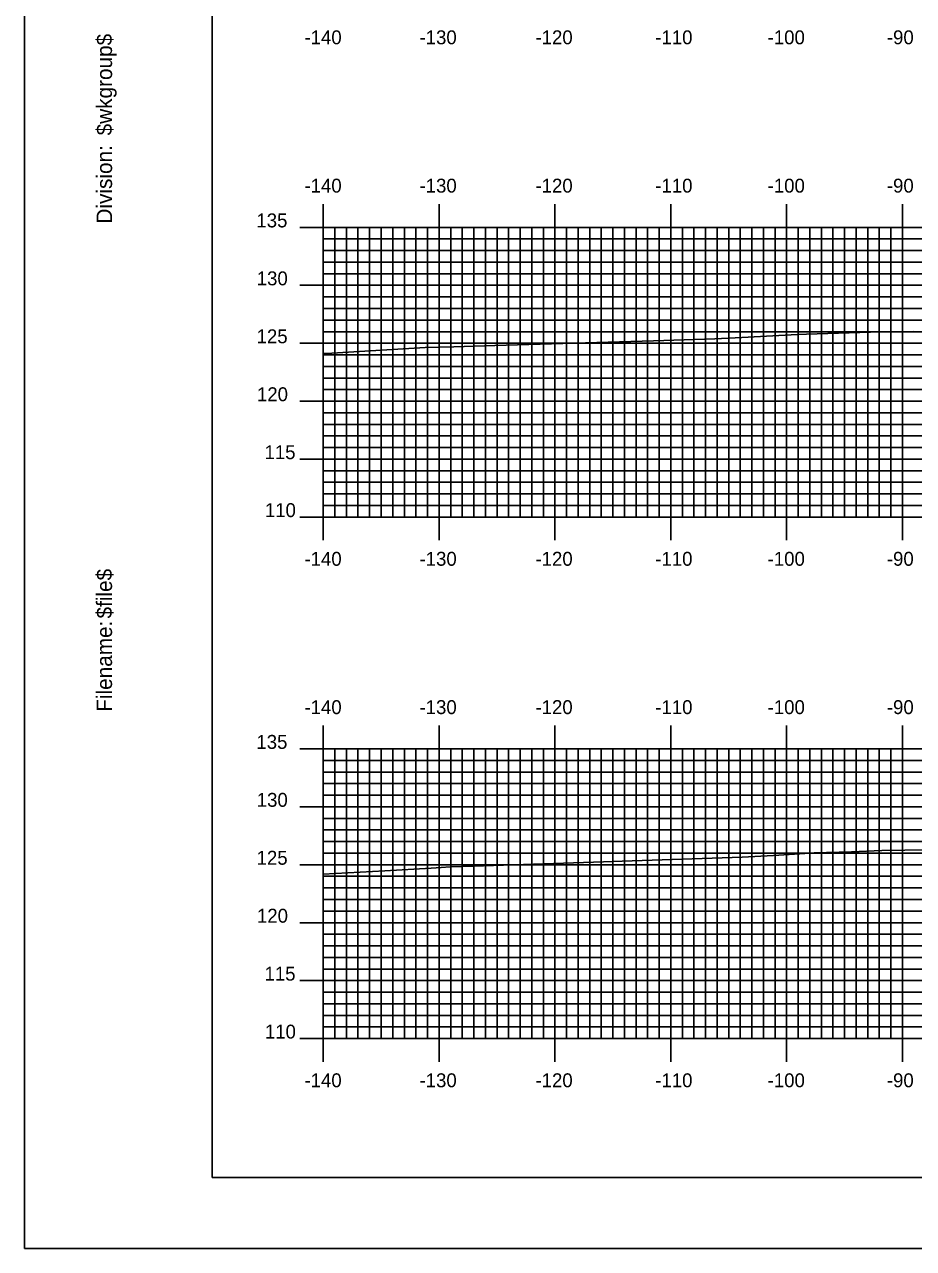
# Model space of a CAD drawing. Extents: x 842569 to 842912, y 363538 to 363758.
# Drawn here: x 842568.6 to 842645.4, y 363537.6 to 363643.2 of the extents above; entities that cross this region are included whole.
import ezdxf

# ---------------------------------------------------------------- set-up
doc = ezdxf.new("R2010")
doc.units = 0
for name, color, linetype in [('BORDER', 7, 'Continuous'), ('H_V ANNOTATION', 7, 'Continuous'), ('M_Roadway_Centerline', 7, 'Continuous'), ('MAJOR', 7, 'Continuous'), ('MINOR', 7, 'Continuous'), ('PLOT BOUNDARY', 7, 'Continuous'), ('S_Roadway_Centerline', 7, 'Continuous')]:
    doc.layers.add(name, color=color, linetype=linetype)

msp = doc.modelspace()

# ---------------------------------------------------------------- linework, layer by layer
at = {"layer": 'BORDER'}
msp.add_lwpolyline([(842584.8, 363543.72), (842904.8, 363543.72), (842904.8, 363753.72), (842584.8, 363753.72)], close=True, dxfattribs=at)
at = {"layer": 'MAJOR'}
for p, q in [((842594.4, 363627.73), (842594.4, 363625.72)), ((842604.4, 363627.73), (842604.4, 363625.72)), ((842614.4, 363627.73), (842614.4, 363625.72)), ((842624.4, 363627.73), (842624.4, 363625.72)), ((842634.4, 363627.73), (842634.4, 363625.72)), ((842644.4, 363627.73), (842644.4, 363625.72)), ((842592.39, 363625.72), (842594.4, 363625.72)), ((842594.4, 363625.72), (842874.4, 363625.72)), ((842594.4, 363600.72), (842594.4, 363625.72)), ((842594.4, 363600.72), (842594.4, 363625.72)), ((842594.4, 363625.72), (842874.4, 363625.72)), ((842604.4, 363600.72), (842604.4, 363625.72)), ((842614.4, 363600.72), (842614.4, 363625.72)), ((842624.4, 363600.72), (842624.4, 363625.72)), ((842634.4, 363600.72), (842634.4, 363625.72)), ((842644.4, 363600.72), (842644.4, 363625.72)), ((842592.39, 363620.72), (842594.4, 363620.72)), ((842594.4, 363620.72), (842874.4, 363620.72)), ((842592.39, 363615.72), (842594.4, 363615.72)), ((842594.4, 363615.72), (842874.4, 363615.72)), ((842592.39, 363610.72), (842594.4, 363610.72)), ((842594.4, 363610.72), (842874.4, 363610.72)), ((842592.39, 363605.72), (842594.4, 363605.72)), ((842594.4, 363605.72), (842874.4, 363605.72)), ((842592.39, 363600.72), (842594.4, 363600.72)), ((842594.4, 363600.72), (842874.4, 363600.72)), ((842594.4, 363600.72), (842874.4, 363600.72)), ((842594.4, 363598.72), (842594.4, 363600.72)), ((842604.4, 363598.72), (842604.4, 363600.72)), ((842614.4, 363598.72), (842614.4, 363600.72)), ((842624.4, 363598.72), (842624.4, 363600.72)), ((842634.4, 363598.72), (842634.4, 363600.72)), ((842644.4, 363598.72), (842644.4, 363600.72)), ((842594.4, 363582.73), (842594.4, 363580.72)), ((842604.4, 363582.73), (842604.4, 363580.72)), ((842614.4, 363582.73), (842614.4, 363580.72)), ((842624.4, 363582.73), (842624.4, 363580.72)), ((842634.4, 363582.73), (842634.4, 363580.72)), ((842644.4, 363582.73), (842644.4, 363580.72)), ((842592.39, 363580.72), (842594.4, 363580.72)), ((842594.4, 363580.72), (842874.4, 363580.72)), ((842594.4, 363555.72), (842594.4, 363580.72)), ((842594.4, 363555.72), (842594.4, 363580.72)), ((842594.4, 363580.72), (842874.4, 363580.72)), ((842604.4, 363555.72), (842604.4, 363580.72)), ((842614.4, 363555.72), (842614.4, 363580.72)), ((842624.4, 363555.72), (842624.4, 363580.72)), ((842634.4, 363555.72), (842634.4, 363580.72)), ((842644.4, 363555.72), (842644.4, 363580.72)), ((842592.39, 363575.72), (842594.4, 363575.72)), ((842594.4, 363575.72), (842874.4, 363575.72)), ((842592.39, 363570.72), (842594.4, 363570.72)), ((842594.4, 363570.72), (842874.4, 363570.72)), ((842592.39, 363565.72), (842594.4, 363565.72)), ((842594.4, 363565.72), (842874.4, 363565.72)), ((842592.39, 363560.72), (842594.4, 363560.72)), ((842594.4, 363560.72), (842874.4, 363560.72)), ((842592.39, 363555.72), (842594.4, 363555.72)), ((842594.4, 363555.72), (842874.4, 363555.72)), ((842594.4, 363555.72), (842874.4, 363555.72)), ((842594.4, 363553.72), (842594.4, 363555.72)), ((842604.4, 363553.72), (842604.4, 363555.72)), ((842614.4, 363553.72), (842614.4, 363555.72)), ((842624.4, 363553.72), (842624.4, 363555.72)), ((842634.4, 363553.72), (842634.4, 363555.72)), ((842644.4, 363553.72), (842644.4, 363555.72))]:
    msp.add_line(p, q, dxfattribs=at)
at = {"layer": 'MINOR'}
for p, q in [((842595.4, 363600.72), (842595.4, 363625.72)), ((842596.4, 363600.72), (842596.4, 363625.72)), ((842597.4, 363600.72), (842597.4, 363625.72)), ((842598.4, 363600.72), (842598.4, 363625.72)), ((842599.4, 363600.72), (842599.4, 363625.72)), ((842600.4, 363600.72), (842600.4, 363625.72)), ((842601.4, 363600.72), (842601.4, 363625.72)), ((842602.4, 363600.72), (842602.4, 363625.72)), ((842603.4, 363600.72), (842603.4, 363625.72)), ((842605.4, 363600.72), (842605.4, 363625.72)), ((842606.4, 363600.72), (842606.4, 363625.72)), ((842607.4, 363600.72), (842607.4, 363625.72)), ((842608.4, 363600.72), (842608.4, 363625.72)), ((842609.4, 363600.72), (842609.4, 363625.72)), ((842610.4, 363600.72), (842610.4, 363625.72)), ((842611.4, 363600.72), (842611.4, 363625.72)), ((842612.4, 363600.72), (842612.4, 363625.72)), ((842613.4, 363600.72), (842613.4, 363625.72)), ((842615.4, 363600.72), (842615.4, 363625.72)), ((842616.4, 363600.72), (842616.4, 363625.72)), ((842617.4, 363600.72), (842617.4, 363625.72)), ((842618.4, 363600.72), (842618.4, 363625.72)), ((842619.4, 363600.72), (842619.4, 363625.72)), ((842620.4, 363600.72), (842620.4, 363625.72)), ((842621.4, 363600.72), (842621.4, 363625.72)), ((842622.4, 363600.72), (842622.4, 363625.72)), ((842623.4, 363600.72), (842623.4, 363625.72)), ((842625.4, 363600.72), (842625.4, 363625.72)), ((842626.4, 363600.72), (842626.4, 363625.72)), ((842627.4, 363600.72), (842627.4, 363625.72)), ((842628.4, 363600.72), (842628.4, 363625.72)), ((842629.4, 363600.72), (842629.4, 363625.72)), ((842630.4, 363600.72), (842630.4, 363625.72)), ((842631.4, 363600.72), (842631.4, 363625.72)), ((842632.4, 363600.72), (842632.4, 363625.72)), ((842633.4, 363600.72), (842633.4, 363625.72)), ((842635.4, 363600.72), (842635.4, 363625.72)), ((842636.4, 363600.72), (842636.4, 363625.72)), ((842637.4, 363600.72), (842637.4, 363625.72)), ((842638.4, 363600.72), (842638.4, 363625.72)), ((842639.4, 363600.72), (842639.4, 363625.72)), ((842640.4, 363600.72), (842640.4, 363625.72)), ((842641.4, 363600.72), (842641.4, 363625.72)), ((842642.4, 363600.72), (842642.4, 363625.72)), ((842643.4, 363600.72), (842643.4, 363625.72)), ((842594.4, 363624.72), (842874.4, 363624.72)), ((842594.4, 363624.72), (842596.4, 363624.72)), ((842594.4, 363623.72), (842874.4, 363623.72)), ((842594.4, 363623.72), (842596.4, 363623.72)), ((842594.4, 363622.72), (842874.4, 363622.72)), ((842594.4, 363622.72), (842596.4, 363622.72)), ((842594.4, 363621.72), (842874.4, 363621.72)), ((842594.4, 363621.72), (842596.4, 363621.72)), ((842594.4, 363619.72), (842874.4, 363619.72)), ((842594.4, 363619.72), (842596.4, 363619.72)), ((842594.4, 363618.72), (842874.4, 363618.72)), ((842594.4, 363618.72), (842596.4, 363618.72)), ((842594.4, 363617.72), (842874.4, 363617.72)), ((842594.4, 363617.72), (842596.4, 363617.72)), ((842594.4, 363616.72), (842874.4, 363616.72)), ((842594.4, 363616.72), (842596.4, 363616.72)), ((842594.4, 363614.72), (842874.4, 363614.72)), ((842594.4, 363614.72), (842596.4, 363614.72)), ((842594.4, 363613.72), (842874.4, 363613.72)), ((842594.4, 363613.72), (842596.4, 363613.72)), ((842594.4, 363612.72), (842874.4, 363612.72)), ((842594.4, 363612.72), (842596.4, 363612.72)), ((842594.4, 363611.72), (842874.4, 363611.72)), ((842594.4, 363611.72), (842596.4, 363611.72)), ((842594.4, 363609.72), (842874.4, 363609.72)), ((842594.4, 363609.72), (842596.4, 363609.72)), ((842594.4, 363608.72), (842874.4, 363608.72)), ((842594.4, 363608.72), (842596.4, 363608.72)), ((842594.4, 363607.72), (842874.4, 363607.72)), ((842594.4, 363607.72), (842596.4, 363607.72)), ((842594.4, 363606.72), (842874.4, 363606.72)), ((842594.4, 363606.72), (842596.4, 363606.72)), ((842594.4, 363604.72), (842874.4, 363604.72)), ((842594.4, 363604.72), (842596.4, 363604.72)), ((842594.4, 363603.72), (842874.4, 363603.72)), ((842594.4, 363603.72), (842596.4, 363603.72)), ((842594.4, 363602.72), (842874.4, 363602.72)), ((842594.4, 363602.72), (842596.4, 363602.72)), ((842594.4, 363601.72), (842874.4, 363601.72)), ((842594.4, 363601.72), (842596.4, 363601.72)), ((842595.4, 363555.72), (842595.4, 363580.72)), ((842596.4, 363555.72), (842596.4, 363580.72)), ((842597.4, 363555.72), (842597.4, 363580.72)), ((842598.4, 363555.72), (842598.4, 363580.72)), ((842599.4, 363555.72), (842599.4, 363580.72)), ((842600.4, 363555.72), (842600.4, 363580.72)), ((842601.4, 363555.72), (842601.4, 363580.72)), ((842602.4, 363555.72), (842602.4, 363580.72)), ((842603.4, 363555.72), (842603.4, 363580.72)), ((842605.4, 363555.72), (842605.4, 363580.72)), ((842606.4, 363555.72), (842606.4, 363580.72)), ((842607.4, 363555.72), (842607.4, 363580.72)), ((842608.4, 363555.72), (842608.4, 363580.72)), ((842609.4, 363555.72), (842609.4, 363580.72)), ((842610.4, 363555.72), (842610.4, 363580.72)), ((842611.4, 363555.72), (842611.4, 363580.72)), ((842612.4, 363555.72), (842612.4, 363580.72)), ((842613.4, 363555.72), (842613.4, 363580.72)), ((842615.4, 363555.72), (842615.4, 363580.72)), ((842616.4, 363555.72), (842616.4, 363580.72)), ((842617.4, 363555.72), (842617.4, 363580.72)), ((842618.4, 363555.72), (842618.4, 363580.72)), ((842619.4, 363555.72), (842619.4, 363580.72)), ((842620.4, 363555.72), (842620.4, 363580.72)), ((842621.4, 363555.72), (842621.4, 363580.72)), ((842622.4, 363555.72), (842622.4, 363580.72)), ((842623.4, 363555.72), (842623.4, 363580.72)), ((842625.4, 363555.72), (842625.4, 363580.72)), ((842626.4, 363555.72), (842626.4, 363580.72)), ((842627.4, 363555.72), (842627.4, 363580.72)), ((842628.4, 363555.72), (842628.4, 363580.72)), ((842629.4, 363555.72), (842629.4, 363580.72)), ((842630.4, 363555.72), (842630.4, 363580.72)), ((842631.4, 363555.72), (842631.4, 363580.72)), ((842632.4, 363555.72), (842632.4, 363580.72)), ((842633.4, 363555.72), (842633.4, 363580.72)), ((842635.4, 363555.72), (842635.4, 363580.72)), ((842636.4, 363555.72), (842636.4, 363580.72)), ((842637.4, 363555.72), (842637.4, 363580.72)), ((842638.4, 363555.72), (842638.4, 363580.72)), ((842639.4, 363555.72), (842639.4, 363580.72)), ((842640.4, 363555.72), (842640.4, 363580.72)), ((842641.4, 363555.72), (842641.4, 363580.72)), ((842642.4, 363555.72), (842642.4, 363580.72)), ((842643.4, 363555.72), (842643.4, 363580.72)), ((842594.4, 363579.72), (842874.4, 363579.72)), ((842594.4, 363579.72), (842596.4, 363579.72)), ((842594.4, 363578.72), (842874.4, 363578.72)), ((842594.4, 363578.72), (842596.4, 363578.72)), ((842594.4, 363577.72), (842874.4, 363577.72)), ((842594.4, 363577.72), (842596.4, 363577.72)), ((842594.4, 363576.72), (842874.4, 363576.72)), ((842594.4, 363576.72), (842596.4, 363576.72)), ((842594.4, 363574.72), (842874.4, 363574.72)), ((842594.4, 363574.72), (842596.4, 363574.72)), ((842594.4, 363573.72), (842874.4, 363573.72)), ((842594.4, 363573.72), (842596.4, 363573.72)), ((842594.4, 363572.72), (842874.4, 363572.72)), ((842594.4, 363572.72), (842596.4, 363572.72)), ((842594.4, 363571.72), (842874.4, 363571.72)), ((842594.4, 363571.72), (842596.4, 363571.72)), ((842594.4, 363569.72), (842874.4, 363569.72)), ((842594.4, 363569.72), (842596.4, 363569.72)), ((842594.4, 363568.72), (842874.4, 363568.72)), ((842594.4, 363568.72), (842596.4, 363568.72)), ((842594.4, 363567.72), (842874.4, 363567.72)), ((842594.4, 363567.72), (842596.4, 363567.72)), ((842594.4, 363566.72), (842874.4, 363566.72)), ((842594.4, 363566.72), (842596.4, 363566.72)), ((842594.4, 363564.72), (842874.4, 363564.72)), ((842594.4, 363564.72), (842596.4, 363564.72)), ((842594.4, 363563.72), (842874.4, 363563.72)), ((842594.4, 363563.72), (842596.4, 363563.72)), ((842594.4, 363562.72), (842874.4, 363562.72)), ((842594.4, 363562.72), (842596.4, 363562.72)), ((842594.4, 363561.72), (842874.4, 363561.72)), ((842594.4, 363561.72), (842596.4, 363561.72)), ((842594.4, 363559.72), (842874.4, 363559.72)), ((842594.4, 363559.72), (842596.4, 363559.72)), ((842594.4, 363558.72), (842874.4, 363558.72)), ((842594.4, 363558.72), (842596.4, 363558.72)), ((842594.4, 363557.72), (842874.4, 363557.72)), ((842594.4, 363557.72), (842596.4, 363557.72)), ((842594.4, 363556.72), (842874.4, 363556.72)), ((842594.4, 363556.72), (842596.4, 363556.72))]:
    msp.add_line(p, q, dxfattribs=at)
at = {"layer": 'PLOT BOUNDARY'}
msp.add_lwpolyline([(842568.61, 363537.6), (842908.61, 363537.6), (842908.61, 363757.6), (842568.61, 363757.6)], close=True, dxfattribs=at)
at = {"layer": 'S_Roadway_Centerline'}
for points in [[(842594.4, 363614.84), (842594.67, 363614.85), (842603.19, 363615.35), (842605.68, 363615.4), (842609.21, 363615.53), (842622.91, 363615.93), (842628.21, 363616.1), (842630.53, 363616.21), (842635.34, 363616.49), (842636.1, 363616.5), (842641.63, 363616.69), (842645.37, 363616.74)], [(842594.4, 363569.91), (842599.72, 363570.2), (842603.71, 363570.41), (842604.58, 363570.47), (842605.36, 363570.55), (842607.36, 363570.61), (842618.6, 363570.98), (842619.33, 363571), (842630.56, 363571.38), (842633.26, 363571.51), (842636.44, 363571.72), (842636.78, 363571.76), (842640, 363571.84), (842642.61, 363571.95), (842646.59, 363572.01)]]:
    msp.add_lwpolyline(points, dxfattribs=at)

# ---------------------------------------------------------------- texts
at = {"layer": 'BORDER'}
for s, p in [('$wkgroup$', (842576.17, 363633.66)), ('Division:', (842576.17, 363626.05)), ('$file$', (842576.17, 363591.97)), ('Filename:', (842576.17, 363583.92))]:
    msp.add_text(s, height=1.339, rotation=90, dxfattribs=at).set_placement(p)
at = {"layer": 'H_V ANNOTATION'}
for s, p in [('-140', (842592.78, 363641.52)), ('-130', (842602.71, 363641.52)), ('-120', (842612.72, 363641.52)), ('-110', (842623.06, 363641.52)), ('-100', (842632.76, 363641.52)), ('-90', (842643.05, 363641.52)), ('-140', (842592.78, 363628.72)), ('-130', (842602.71, 363628.72)), ('-120', (842612.72, 363628.72)), ('-110', (842623.06, 363628.72)), ('-100', (842632.76, 363628.72)), ('-90', (842643.05, 363628.72)), ('135', (842588.63, 363625.72)), ('130', (842588.66, 363620.72)), ('125', (842588.65, 363615.72)), ('120', (842588.68, 363610.72)), ('115', (842589.33, 363605.72)), ('110', (842589.36, 363600.72)), ('-140', (842592.78, 363596.52)), ('-130', (842602.71, 363596.52)), ('-120', (842612.72, 363596.52)), ('-110', (842623.06, 363596.52)), ('-100', (842632.76, 363596.52)), ('-90', (842643.05, 363596.52)), ('-140', (842592.78, 363583.72)), ('-130', (842602.71, 363583.72)), ('-120', (842612.72, 363583.72)), ('-110', (842623.06, 363583.72)), ('-100', (842632.76, 363583.72)), ('-90', (842643.05, 363583.72)), ('135', (842588.63, 363580.72)), ('130', (842588.66, 363575.72)), ('125', (842588.65, 363570.72)), ('120', (842588.68, 363565.72)), ('115', (842589.33, 363560.72)), ('110', (842589.36, 363555.72)), ('-140', (842592.78, 363551.52)), ('-130', (842602.71, 363551.52)), ('-120', (842612.72, 363551.52)), ('-110', (842623.06, 363551.52)), ('-100', (842632.76, 363551.52)), ('-90', (842643.05, 363551.52))]:
    msp.add_text(s, height=1.2, dxfattribs=at).set_placement(p)
at = {"layer": 'M_Roadway_Centerline'}
for s, p in [('C', (842635.34, 363616.49)), ('L', (842635.34, 363616.48)), ('C', (842603.19, 363615.35)), ('L', (842603.19, 363615.34)), ('C', (842636.77, 363571.76)), ('L', (842636.78, 363571.75)), ('C', (842605.36, 363570.55)), ('L', (842605.36, 363570.54))]:
    msp.add_text(s, height=0.0146, dxfattribs=at).set_placement(p)
at = {"layer": 'MAJOR'}
for p in [(842594.39, 363600.72), (842594.39, 363555.72)]:
    msp.add_text('-', height=0.012, dxfattribs=at).set_placement(p)

doc.saveas('drawing.dxf')
